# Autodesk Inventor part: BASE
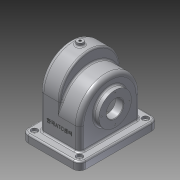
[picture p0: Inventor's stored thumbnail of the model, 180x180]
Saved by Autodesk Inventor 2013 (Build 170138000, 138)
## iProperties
Created: 2017-11
Part Number: BASE
Material: 알루미늄 6061
Document SubType Name: Modeling
Designer: Administrator
Density: 2.71 g/cm^3
Mass: 1097.64 g
Surface Area: 1194.15 cm^2
Volume: 405.032 cm^3
Author: Administrator
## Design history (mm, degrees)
sketch "스케치1"
  geometry: L1 (-58, 0)-(-58, -65); L2 (-58, -65)-(58, -65); L3 (58, -65)-(58, 0); A1 r 58 centre (0, 0) between (58, 0) and (-58, 0); 1 further point
  constraints: 6 end point, 2 point on circle, 2 tangent, 1 centre point, 1 coincident, 1 perpendicular, 1 vertical, 1 vertical alignment
  dimensions: "d0" = 116 diameter of A1; "d3" = 65 distance of L1.start L1.end
extrude "돌출1" new body sketch "스케치1" distance "d4" = 38; taper "d5" = 0 deg
sketch "스케치2"
  geometry: L1 (0, 58)-(65, 58) reference; L2 (65, 58)-(65, -58) reference; L3 (65, -58)-(0, -58) reference; L4 (65, -58)-(65, 58); L5 (65, 58)-(23, 58); L6 (55.666, -58)-(23, -58); L7 (55.666, -58)-(65, -58); A1 r 58 centre (0, 0) between (0, 58) and (0, -58) reference; A2 r 58 centre (23, 0) between (23, 58) and (23, -58); 1 further point
  constraints: 8 end point, 2 collinear, 2 point on circle, 2 tangent, 1 centre point, 1 horizontal alignment, 1 point on line, 1 vertical alignment
  dimensions: "d6" = 116 diameter of A2; "d8" = 42 distance from line of L2 A2.centre
extrude "돌출2" join sketch "스케치2" distance "d9" = 38; taper "d10" = 0 deg
feature "쉘1" dims "d11" = 5
sketch "스케치4"
  geometry: L1 (-71, 111)-(-71, 5) reference; L2 (-71, 5)-(-5, 5) reference; L3 (-5, 5)-(-5, 111) reference; L4 (-5, 111)-(-71, 111) reference; L5 (-76, 0)-(-76, 116) reference; L6 (-76, 116)-(0, 116) reference; L7 (0, 116)-(0, 0) reference; L8 (0, 0)-(-76, 0) reference; L9 (17, 133)-(-93, 133); L10 (-93, 133)-(-93, -17); L11 (-93, -17)-(17, -17); L12 (17, -17)-(17, 133); 1 further point
  constraints: 8 end point, 3 other
  dimensions: "d12" = 110 distance of L9.start L9.end; "d14" = 150 distance of L9.end L10.end (derived)
extrude "돌출3" join sketch "스케치4" distance "d15" = 15; taper "d16" = 0 deg
fillet "모깎기1" dims "d17" = 12
sketch "스케치7"
  geometry: L1 (-80, 75)-(-65, 75) reference; L2 (-65, 75)-(-65, 58) reference; L3 (-65, 58)-(-65, -58) reference; L4 (-65, -58)-(-65, -75) reference; L5 (-65, -75)-(-80, -75) reference; L6 (-80, -75)-(-80, 75) reference; L7 (-65, 58)-(0, 58) reference; L8 (0, -58)-(-65, -58) reference; C1 r 37.5 at (-15, 0); A1 r 58 centre (0, 0) between (0, -58) and (0, 58) reference; 1 further point
  constraints: 1 centre point, 1 horizontal alignment
  dimensions: "d18" = 75 diameter of C1; "d20" = 65 distance from line of L6 C1.centre
extrude "돌출4" join sketch "스케치7" distance "d21" = 9; taper "d22" = 0 deg
sketch "스케치8"
  geometry: L1 (23, 58)-(65, 58) reference; L2 (65, 58)-(65, 75) reference; L3 (65, 75)-(80, 75) reference; L4 (80, 75)-(80, -75) reference; L5 (80, -75)-(65, -75) reference; L6 (65, -75)-(65, -58) reference; L7 (65, -58)-(65, 58) reference; L8 (65, -58)-(23, -58) reference; C1 r 31 at (15, 0); A1 r 58 centre (23, 0) between (23, 58) and (23, -58) reference; 1 further point
  constraints: 1 centre point, 1 horizontal alignment
  dimensions: "d23" = 62 diameter of C1; "d25" = 65 distance from line of L4 C1.centre
extrude "돌출5" join sketch "스케치8" distance "d26" = 10; taper "d27" = 0 deg
sketch "스케치9"
  geometry: L1 (50, -73.909)-(50, 73.909) reference; L2 (50, 73.909)-(65, 73.909) reference; L3 (65, 73.909)-(65, -73.909) reference; L4 (65, -73.909)-(50, -73.909) reference; C1 r 31 at (0, 0) reference; C2 r 16 at (0, 0); 1 further point
  constraints: 1 centre point, 1 coincident
  dimensions: "d28" = 32 diameter of C2
extrude "돌출6" cut sketch "스케치9" stored distance "d30" = 10; taper "d31" = 0 deg
chamfer "모따기1" distance "d32" = 1; stored, may be unused: second distance "d33" = 2, angle "d34" = 45 deg
fillet "모깎기2" dims "d35" = 3
fillet "모깎기3" dims "d36" = 3
hole "구멍1" diameter "d39" = 5; stored, may be unused: countersink angle "d43" = 90 deg, drill point angle "d45" = 118 deg; dims "d37" = 10, "d38" = 10, "d40" = 6, "d41" = 12, "d42" = 5, "d44" = 8
node "작업 평면1"
sketch "스케치11"
  geometry: L1 (55, -66.317)-(55, -59.683) reference; L2 (55, -59.683)-(50, -59.683) reference; L3 (50, -59.683)-(50, 59.683) reference; L4 (50, 59.683)-(55, 59.683) reference; L5 (55, 59.683)-(55, 66.317) reference; L6 (55, 66.317)-(50, 66.317) reference; L7 (50, 66.317)-(50, 73.909) reference; L8 (50, 73.909)-(65, 73.909) reference; L9 (65, 73.909)-(65, -73.909) reference; L10 (65, -73.909)-(50, -73.909) reference; L11 (50, -73.909)-(50, -66.317) reference; L12 (50, -66.317)-(55, -66.317) reference; C1 r 31 at (0, 0) reference; C2 r 17 at (0, 0) reference; C3 r 26 at (0, 0); 2 further points
  constraints: 1 centre point, 1 coincident, 1 horizontal alignment
  dimensions: "d46" = 52 diameter of C3; "d48" = 26 distance of C1.centre point (-26, 0)
hole "구멍2" sketch "스케치11" at (-26, 0) diameter "d49" = 2.459; stored, may be unused: countersink angle "d53" = 90 deg, drill point angle "d55" = 118 deg; dims "d50" = 6, "d51" = 12, "d52" = 5, "d54" = 8
sketch "스케치12"
  geometry: L1 (-65, 74.314)-(-50, 74.314) reference; L2 (-50, 74.314)-(-50, 67.472) reference; L3 (-50, 67.472)-(-55, 67.472) reference; L4 (-55, 67.472)-(-55, 58.528) reference; L5 (-55, 58.528)-(-50, 58.528) reference; L6 (-50, 58.528)-(-50, -58.528) reference; L7 (-50, -58.528)-(-55, -58.528) reference; L8 (-55, -58.528)-(-55, -67.472) reference; L9 (-55, -67.472)-(-50, -67.472) reference; L10 (-50, -67.472)-(-50, -74.314) reference; L11 (-50, -74.314)-(-65, -74.314) reference; L12 (-65, -74.314)-(-65, 74.314) reference; C1 r 37.5 at (0, 0) reference; C2 r 17 at (0, 0) reference; 2 further points
  constraints: 1 horizontal alignment
  dimensions: "d59" = 29 distance of point (29, 0) C1.centre
hole "구멍3" sketch "스케치12" at (29, 0) diameter "d60" = 2.459; stored, may be unused: countersink angle "d64" = 90 deg, drill point angle "d66" = 118 deg; dims "d61" = 6, "d62" = 12, "d63" = 5, "d65" = 8
fillet "모깎기4" dims "d70" = 3
node "작업 평면2"
sketch "스케치13"
  geometry: L1 (0, 0)-(35, 0) reference; L2 (35, 116)-(35, 0) reference; L3 (0, 116)-(35, 116) reference; L4 (35, 116)-(76, 116) reference; L5 (41, 5.819)-(41, 110.181) reference; L6 (35, 0)-(76, 0) reference; L7 (-9, 95.5)-(-9, 20.5) reference; L8 (86, 27)-(86, 89) reference; L9 (0, 3)-(0, 113) reference; L10 (0, 0)-(0, 116) reference; L11 (76, 116)-(76, 0) reference; C1 r 6 at (19, 58); 4 further points
  constraints: 1 centre point, 1 horizontal alignment, 1 midpoint, 4 other
  dimensions: "d74" = 19 distance from line of C1.centre L9; "d75" = 12 diameter of C1
extrude "돌출7" join sketch "스케치13" stored distance "d76" = 10; taper "d77" = 0 deg
fillet "모깎기6" dims "d78" = 3
hole "구멍4" diameter "d81" = 4.459; stored, may be unused: countersink angle "d85" = 90 deg, drill point angle "d87" = 118 deg; dims "d79" = 10, "d80" = 10, "d82" = 6, "d83" = 12, "d84" = 5, "d86" = 8
sketch "스케치15"
  geometry: L1 (42.683, -47)-(49.317, -47) reference; L2 (49.317, -47)-(49.317, -42) reference; L3 (49.317, -42)-(55, -42) reference; L4 (58, -45)-(58, -57) reference; L5 (58, -57)-(-52, -57) reference; L6 (-52, -57)-(-52, -45) reference; L7 (-49, -42)-(-43.317, -42) reference; L8 (-43.317, -42)-(-43.317, -47) reference; L9 (-43.317, -47)-(-36.683, -47) reference; L10 (-36.683, -47)-(-36.683, -42) reference; L11 (42.683, -42)-(42.683, -47) reference; L12 (-35, 23)-(0, 23) reference; L13 (0, 23)-(0, 0) reference; L14 (0, 0)-(41, 0) reference; L15 (-21.887, -13.398)-(27.887, -13.398); L16 (27.887, -13.398)-(27.887, -20.602); L17 (27.887, -20.602)-(-21.887, -20.602); L18 (-21.887, -20.602)-(-21.887, -13.398); L19 (-35, -42)-(-35, 23) reference; L20 (-36.683, -42)-(-35, -42) reference; L21 (-35, -42)-(41, -42) reference; L22 (41, -42)-(42.683, -42) reference; L23 (41, 0)-(41, -42) reference; A1 r 3 centre (55, -45) between (58, -45) and (55, -42) reference; A2 r 3 centre (-49, -45) between (-49, -42) and (-52, -45) reference; 2 further points
  constraints: 2 midpoint, 2 other
  dimensions: "d88" = 3.60244 distance of point (-21.887, -17) L15.start; "d90" = 7.20489 distance between parallel lines of L17 L15 (derived); "d91" = 49.77477 distance of L15.start L15.end; "d98" = 40 distance from line of point (-21.887, -17) L5
feature "엠보싱1" sketch "스케치15" dims "d0" = 116, "d3" = 65, "d94" = 0.5, "d95" = 0
fillet "모깎기7" dims "d96" = 8
fillet "모깎기8" dims "d97" = 3
node "솔리드1"
mirror "대칭1"
mirror "대칭2"
pattern_circular "원형 패턴1" dims angle "d57" = 360 deg
pattern_circular "원형 패턴2" dims angle "d68" = 360 deg
node "투영된 루프1"
node "투영된 루프2"
node "절단 모서리 투영1"
node "절단 모서리 투영2"
node "절단 모서리 투영4"
node "절단 모서리 투영5"
node "절단 모서리 투영6"
node "절단 모서리 투영7"
node "절단 모서리 투영8"
node "절단 모서리 투영9"
other parameters: "d72" = -144
